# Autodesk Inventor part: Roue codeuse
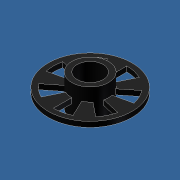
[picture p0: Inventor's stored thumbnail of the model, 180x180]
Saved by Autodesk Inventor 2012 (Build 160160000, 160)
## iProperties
Created: 2011-10
Part Number: Roue codeuse
Material: ABS (plastique)
Document SubType Name: Modeling
Designer: Laur
Mass: 0.0367757 g
Surface Area: 1.54299 cm^2
Volume: 0.034694 cm^3
Density: 1.06 g/cm^3
Author: Laur
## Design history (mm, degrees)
sketch "Esquisse3"
  geometry: L1 (1.24, -0.2)-(-1.24, -0.2) reference; L2 (1.24, -3.9)-(-1.24, -3.9) reference; L3 (0, -0.2)-(0, -3.9); L4 (-1.24, -0.2)-(-1.75, -0.2); L5 (-1.75, -1.45)-(-4, -1.45); L6 (-4, -1.45)-(-4, -1.95); L7 (-4, -1.95)-(-1.75, -1.95); L8 (-1.75, -1.95)-(-1.75, -3.2); L9 (-1.75, -3.2)-(-1.24, -3.2); L10 (-1.75, -1.45)-(-1.75, -0.2); L11 (-1.24, -0.2)-(-1.24, -3.2); L12 (-1.24, -0.2)-(-1.24, -3.2)
  constraints: 20 end point, 4 perpendicular, 3 parallel, 2 midpoint, 2 point on line, 1 collinear
  dimensions: "d0" = 3.5 diameter of L8 L3; "d1" = 3.5 diameter of L10 L3 (= d0); "d2" = 3 distance between parallel lines of L9 L4; "d3" = 0.5 distance between parallel lines of L7 L5; "d4" = 8 diameter of L6 L3; "d5" = 1.25 distance between parallel lines of L4 L5 (= 0.5 x d2 - 0.5 x d3); "d18" = 2.48 diameter of L11 L3 (derived)
revolve "forme générale" sketch "Esquisse3" stored, may be unused: angle "d6" = 90 deg
sketch "Esquisse4"
  geometry: L1 (0.767, 1.573)-(1.534, 3.146); L2 (0, 1.75)-(0, 3.5); L3 (0, 0)-(0.767, 1.573); L4 (0, 1.75)-(0, 0); C1 r 4 at (0, 0) reference; C2 r 4 at (0, 0) reference; A1 r 1.75 centre (0, 0) between (0, 1.75) and (0.767, 1.573) reference; A2 r 3.5 centre (0, 0) between (0, 3.5) and (1.534, 3.146)
  constraints: 8 end point, 4 point on circle, 2 collinear, 1 centre point, 1 coincident, 1 vertical
  dimensions: "d7" = 0.5 radial gap between concentric circles of A2 C2; "d8" = 26 deg angle of L1 L2
extrude "ouverture 26°" cut sketch "Esquisse4" stored distance "d13" = 10; taper "d14" = 0 deg
pattern_circular "Réseau 7 ouvertures" dims angle "d16" = 360 deg
node "Solide1"
node "Corps solides"
node "Corps surfaciques"
node "Référence2"
node "Référence3"
